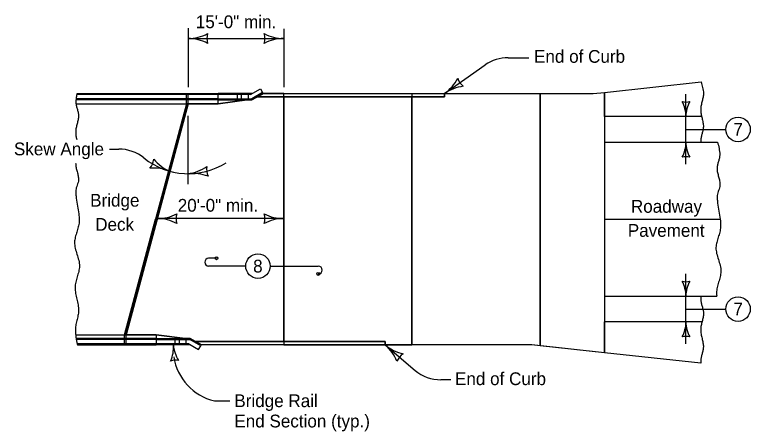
# Model space of a CAD drawing. Extents: x 9234 to 81668, y 5635 to 15999.
# Drawn here: x 18608 to 19530, y 8752 to 9275 of the extents above; entities that cross this region are included whole.
import ezdxf

# ---------------------------------------------------------------- set-up
doc = ezdxf.new("R2010")
doc.units = 0
for name, color, linetype in [('Annotation', 7, 'Continuous'), ('PS_BOLT', 7, 'Continuous'), ('PS_CONST', 7, 'Continuous'), ('PS_DIM', 7, 'Continuous'), ('Revetment', 7, 'Continuous')]:
    doc.layers.add(name, color=color, linetype=linetype)

msp = doc.modelspace()

# ---------------------------------------------------------------- linework, layer by layer
at = {"layer": 'Annotation'}
for p, q in [((18903.37, 9174.38), (18915.74, 9181.52)), ((18915.74, 9181.52), (18918.42, 9176.88)), ((18862.78, 9174.38), (18685.5, 9174.38)), ((18685.89, 9175.72), (18862.78, 9175.72)), ((18823, 9162.99), (18823, 9175.72)), ((18824.99, 9162.99), (18824.99, 9175.72)), ((18862.78, 9162.99), (18862.78, 9175.72)), ((18905.7, 9175.72), (18862.78, 9175.72)), ((18886.41, 9174.38), (18886.41, 9167.68)), ((18891.77, 9174.38), (18891.77, 9167.68)), ((18900.32, 9174.38), (18900.32, 9167.68)), ((18918.42, 9176.88), (18904.81, 9169.02)), ((18919.1, 9175.72), (18905.17, 9167.68)), ((18919.1, 9175.72), (18918.42, 9176.88)), ((18684.38, 9162.99), (18862.78, 9162.99)), ((18862.78, 9167.68), (18684.42, 9167.68)), ((18862.78, 9169.02), (18684.55, 9169.02)), ((18823, 9162.99), (18745.42, 8873.46)), ((18862.78, 9169.02), (18904.81, 9169.02)), ((18862.78, 9167.68), (18905.17, 9167.68)), ((18862.78, 9162.99), (18898.81, 9167.68)), ((18684.01, 8873.46), (18785.2, 8873.46)), ((18785.34, 8868.77), (18684.54, 8868.77)), ((18785.2, 8867.42), (18684.74, 8867.42)), ((18745.42, 8860.72), (18745.42, 8873.46)), ((18747.41, 8860.72), (18747.41, 8873.46)), ((18785.2, 8873.46), (18785.2, 8860.72)), ((18785.2, 8873.46), (18821.23, 8868.77)), ((18785.2, 8868.77), (18827.59, 8868.77)), ((18785.2, 8867.42), (18827.23, 8867.42)), ((18808.83, 8862.06), (18808.83, 8868.77)), ((18814.19, 8862.06), (18814.19, 8868.77)), ((18822.74, 8862.06), (18822.74, 8868.77)), ((18840.85, 8859.56), (18827.23, 8867.42)), ((18834.45, 8864.81), (18827.59, 8868.77)), ((18785.2, 8862.06), (18685.88, 8862.06)), ((18686.3, 8860.72), (18785.2, 8860.72)), ((18828.12, 8860.72), (18785.2, 8860.72)), ((18825.79, 8862.06), (18838.16, 8854.92)), ((18838.16, 8854.92), (18840.85, 8859.56)), ((18841.52, 8860.73), (18840.85, 8859.56))]:
    msp.add_line(p, q, dxfattribs=at)
for points in [[(18903.37, 9174.38), (18862.78, 9174.38), (18862.78, 9174.38), (18862.78, 9174.38)], [(18825.79, 8862.06), (18785.2, 8862.06), (18785.2, 8862.06), (18785.2, 8862.06)]]:
    msp.add_lwpolyline(points, dxfattribs=at)
at = {"layer": 'PS_CONST'}
for centre in [(18860.67, 8969.26), (18988.35, 8949.59)]:
    msp.add_circle(centre, 1.78, dxfattribs=at)
for centre, radius, start, end in [((18764.28, 8857.49), 42.5, 336.29398, 4.36647), ((18849.04, 8863.96), 42.5, 184.36647, 212.43895), ((18809.37, 8825.19), 16.42, 76.63311, 112.09982)]:
    msp.add_arc(centre, radius, start, end, dxfattribs=at)
at = {"layer": 'PS_DIM'}
for p, q in [((18824.99, 9257.53), (18824.99, 9183.59)), ((18945.06, 9256.8), (18945.06, 9183.59)), ((18824.99, 9244.76), (18945.06, 9244.76)), ((19226.51, 9220.7), (19252.26, 9220.7)), ((19146.63, 9175.72), (19197.79, 9211.62)), ((19347.18, 9177.21), (19468.53, 9190.24)), ((18685.89, 9175.72), (18685.89, 9175.72)), ((19449.48, 9087.36), (19449.48, 9174.78)), ((18824.99, 9062.36), (18824.99, 9147.74)), ((19469.3, 9146.9), (19347.18, 9146.9)), ((19449.48, 9130.77), (19478.95, 9130.77)), ((19478.95, 9130.77), (19499.51, 9130.77)), ((19347.18, 9114.73), (19489.28, 9114.73)), ((18726.48, 9106.13), (18738.27, 9106.13)), ((18945.06, 9018.99), (18786.4, 9018.99)), ((19347.18, 9018.22), (19492.49, 9018.22)), ((18860.67, 8969.26), (18850.84, 8969.26)), ((18897.33, 8959.43), (18850.85, 8959.43)), ((18928.05, 8959.43), (18988.35, 8959.43)), ((19449.48, 8862.17), (19449.48, 8949.6)), ((19347.18, 8921.71), (19488.14, 8921.71)), ((19449.48, 8905.58), (19478.95, 8905.58)), ((19478.95, 8905.58), (19499.51, 8905.58)), ((19469.74, 8889.54), (19347.18, 8889.54)), ((18685.95, 8861.81), (18686.3, 8860.72)), ((19072.22, 8860.7), (19109.93, 8828.78)), ((19468.15, 8837.91), (19347.18, 8850.9)), ((19154.51, 8816.94), (19142.24, 8816.94)), ((18857.99, 8790.62), (18877.5, 8790.62))]:
    msp.add_line(p, q, dxfattribs=at)
for points in [[(18945.06, 8864.79), (18834.45, 8864.81), (18827.6, 8868.77), (18822.74, 8868.77), (18821.23, 8868.77), (18785.21, 8873.46), (18747.41, 8873.46), (18824.99, 9162.99), (18862.79, 9162.99), (18898.81, 9167.68), (18905.17, 9167.68), (18905.18, 9167.68), (18910.51, 9170.76), (18912.13, 9171.7), (18945.06, 9171.7)], [(19146.63, 9175.74), (19146.63, 9171.7), (18912.13, 9171.7), (18919.09, 9175.72)], [(19146.63, 9171.7), (19146.63, 9175.72), (19266.76, 9175.72), (19266.76, 8859.54), (19256.29, 8860.66), (19105.91, 8860.69), (19105.91, 9171.7)], [(19347.18, 9177.21), (19347.18, 8850.9), (19266.76, 8859.54), (19266.76, 9175.72), (19333.26, 9175.72)], [(19072.22, 8864.77), (19072.22, 8860.72), (18841.52, 8860.73), (18834.45, 8864.81)]]:
    msp.add_lwpolyline(points, close=True, dxfattribs=at)
msp.add_lwpolyline([(19072.22, 8860.7), (19072.22, 8864.77), (18945.06, 8864.79), (18945.06, 9171.7), (19105.91, 9171.7), (19105.91, 8860.69), (19072.22, 8860.7)], dxfattribs=at)
for centre in [(19514.87, 9130.77), (18912.69, 8959.43), (18912.69, 8959.43), (19514.87, 8905.58)]:
    msp.add_circle(centre, 15.36, dxfattribs=at)
for centre, radius, start, end in [((18824.99, 9296.98), 52.23, 270, 298.07249), ((18868.78, 9244.75), 20.17, 162.26665, 197.73335), ((18901.26, 9244.75), 20.17, 342.26665, 17.73335), ((18945.06, 9296.98), 52.23, 241.92751, 270), ((18824.99, 9192.52), 52.23, 61.92751, 90), ((18945.06, 9192.52), 52.23, 90, 118.07249), ((19226.51, 9170.7), 50, 90, 125.06176), ((19116.63, 9218.47), 52.23, 305.06176, 333.13425), ((19182.47, 9200.87), 20.17, 197.32841, 232.79511), ((19176.63, 9132.97), 52.23, 96.98927, 125.06176), ((19449.48, 9180.59), 15.52, 252.26665, 287.73335), ((19409.31, 9146.9), 40.18, 360, 28.07249), ((19489.66, 9146.9), 40.18, 151.92751, 180), ((19409.31, 9114.73), 40.18, 331.92751, 360), ((19489.66, 9114.73), 40.18, 180, 208.07249), ((18738.27, 9056.13), 50, 51.03773, 90), ((18825.49, 9163.98), 88.71, 231.03773, 302.32505), ((18761.85, 9095.12), 20.17, 319.76199, 355.22869), ((18822.3, 9126.6), 52.23, 219.42285, 247.49534), ((19449.48, 9081.05), 15.52, 72.26665, 107.73335), ((18782.32, 9030.1), 52.23, 67.49534, 95.56783), ((18818.79, 9127.13), 52.23, 276.80986, 304.88235), ((18868.47, 9080.46), 20.17, 169.07651, 204.54321), ((18831.18, 9023.41), 52.23, 68.73737, 96.80986), ((18786.42, 9071.21), 52.23, 270, 298.07249), ((18830.21, 9018.99), 20.17, 162.26665, 197.73335), ((18901.26, 9018.99), 20.17, 342.26665, 17.73335), ((18945.06, 9071.21), 52.23, 241.92751, 270), ((18786.42, 8966.76), 52.23, 61.92751, 90), ((18945.06, 8966.76), 52.23, 90, 118.07249), ((18850.84, 8964.34), 4.92, 90, 270), ((18988.35, 8954.51), 4.92, 270, 90), ((19449.48, 8955.4), 15.52, 252.26665, 287.73335), ((19409.31, 8921.71), 40.18, 360, 28.07249), ((19489.66, 8921.71), 40.18, 151.92751, 180), ((19409.31, 8889.54), 40.18, 331.92751, 360), ((19489.66, 8889.54), 40.18, 180, 208.07249), ((19449.48, 8855.86), 15.52, 72.26665, 107.73335), ((19038.47, 8820.84), 52.23, 21.68043, 49.75292), ((19105.96, 8900.57), 52.23, 229.75292, 257.82541), ((19038.47, 8820.84), 52.23, 49.75179, 49.75293), ((19105.64, 8832.41), 20.17, 122.01957, 157.48627), ((18873.12, 8855.55), 66.66, 188.48278, 256.88228), ((19142.24, 8866.94), 50, 229.75292, 270)]:
    msp.add_arc(centre, radius, start, end, dxfattribs=at)
for points in [[(18685.89, 9175.72), (18684.77, 9170.71), (18684.47, 9168.19), (18684.29, 9165.67), (18684.67, 9161.23), (18685.82, 9156.79), (18687.04, 9152.35), (18687.6, 9147.9), (18687.06, 9142.81), (18685.85, 9137.72), (18684.63, 9132.62), (18684.22, 9130.07), (18684.05, 9127.52), (18684.44, 9122.81), (18685.38, 9118.09)], [(18684.04, 9088.39), (18684.6, 9083.14), (18685.9, 9077.87), (18687.16, 9072.6), (18687.6, 9067.34), (18687.04, 9064.12), (18685.96, 9060.94), (18684.87, 9057.76), (18684.29, 9054.55), (18684.29, 9049.64), (18684.72, 9044.7), (18686.31, 9034.74), (18687.91, 9024.8), (18688.44, 9017.41), (18688.4, 9014.97), (18687.37, 9008.55), (18685.46, 9002.14), (18683.58, 8995.73), (18682.61, 8989.3), (18682.79, 8985.55), (18683.46, 8981.79), (18685.63, 8974.29), (18687.83, 8966.79), (18688.76, 8959.28), (18688.48, 8955.94), (18687.84, 8952.6), (18685.99, 8945.91), (18684.17, 8939.22), (18683.33, 8932.53), (18684.03, 8925.32), (18685.56, 8918.08), (18687.07, 8910.84), (18687.67, 8903.6), (18686.94, 8897.36), (18685.49, 8891.12), (18684.15, 8884.89), (18683.69, 8878.65), (18683.94, 8874.43), (18684.35, 8870.2), (18685.95, 8861.81)]]:
    msp.add_spline(points, degree=3, dxfattribs=at)
at = {"layer": 'Revetment'}
for p, q in [((18919.09, 9175.72), (18905.18, 9167.68)), ((18912.13, 9171.7), (19146.63, 9171.7)), ((18945.06, 9175.72), (18919.09, 9175.72)), ((18945.06, 9018.22), (18945.06, 9175.72)), ((18945.06, 9175.72), (19105.91, 9175.72)), ((19105.91, 9175.72), (19105.91, 9018.22)), ((19105.91, 9175.72), (19333.26, 9175.72)), ((19146.63, 9175.72), (19146.63, 9171.7)), ((19266.76, 9175.72), (19266.76, 8859.54)), ((19333.26, 9175.72), (19347.18, 9177.21)), ((19347.18, 9146.9), (19347.18, 9177.21)), ((19347.18, 9177.21), (19347.18, 9018.22)), ((18824.99, 9162.99), (18747.41, 8873.46)), ((18823, 9162.99), (18784.21, 9018.22)), ((18862.79, 9162.99), (18823, 9162.99)), ((18898.81, 9167.68), (18862.79, 9162.99)), ((18905.18, 9167.68), (18898.81, 9167.68)), ((19347.18, 9146.9), (19347.18, 9114.73)), ((18745.42, 8873.46), (18784.21, 9018.22)), ((18945.06, 9018.22), (18945.06, 8860.73)), ((19105.91, 8860.69), (19105.91, 9018.22)), ((19347.18, 9018.22), (19347.18, 8850.9)), ((19347.18, 8850.9), (19347.18, 8889.54)), ((18785.21, 8873.46), (18745.42, 8873.46)), ((18821.23, 8868.77), (18785.21, 8873.46)), ((18827.6, 8868.77), (18821.23, 8868.77)), ((18841.51, 8860.73), (18827.6, 8868.77)), ((18834.45, 8864.81), (19072.22, 8864.74)), ((18945.06, 8860.73), (18841.51, 8860.73)), ((18945.06, 8860.73), (19105.91, 8860.69)), ((19072.22, 8860.7), (19072.22, 8864.74)), ((19256.29, 8860.66), (19105.91, 8860.69)), ((19347.18, 8850.9), (19256.29, 8860.66))]:
    msp.add_line(p, q, dxfattribs=at)
for points in [[(19468.53, 9190.24), (19469.34, 9186.74), (19470.36, 9183.23), (19471.23, 9179.72), (19471.6, 9176.21), (19471.05, 9171.12), (19469.84, 9166.03), (19468.62, 9160.93), (19468.04, 9155.84), (19468.55, 9150.39), (19469.72, 9144.94), (19470.87, 9139.48), (19471.36, 9134.04), (19470.84, 9129.76), (19469.74, 9125.5), (19468.63, 9121.24), (19468.04, 9116.98), (19468.09, 9114.73)], [(19489.28, 9114.73), (19491, 9106.96), (19491.69, 9103.07), (19491.94, 9099.2), (19491.42, 9094.92), (19490.32, 9090.66), (19489.21, 9086.4), (19488.62, 9082.14), (19489.13, 9076.82), (19490.44, 9071.48), (19491.72, 9066.14), (19492.18, 9060.81), (19491.61, 9057.59), (19490.53, 9054.41), (19489.45, 9051.23), (19488.86, 9048.02), (19488.86, 9043.11), (19489.3, 9038.17), (19490.88, 9028.22), (19492.48, 9018.27), (19493.01, 9010.88), (19492.97, 9008.44), (19491.94, 9002.02), (19490.04, 8995.61), (19488.15, 8989.2), (19487.18, 8982.77), (19487.36, 8979.02), (19488.03, 8975.27), (19490.21, 8967.76), (19492.4, 8960.26), (19493.33, 8952.76), (19493.05, 8949.41), (19492.42, 8946.07), (19490.56, 8939.39), (19488.74, 8932.7), (19487.91, 8926), (19488.14, 8921.71)], [(19468.6, 8921.71), (19468.28, 8917.93), (19468.66, 8913.48), (19469.82, 8909.04), (19471.03, 8904.6), (19471.6, 8900.16), (19471.05, 8895.07), (19469.84, 8889.97), (19468.62, 8884.88), (19468.04, 8879.78), (19468.55, 8874.34), (19469.72, 8868.88), (19470.87, 8863.42), (19471.36, 8857.98), (19470.84, 8853.71), (19469.74, 8849.45), (19468.63, 8845.19), (19468.04, 8840.92), (19468.15, 8837.91)]]:
    msp.add_spline(points, degree=3, dxfattribs=at)

# ---------------------------------------------------------------- texts
at = {"layer": 'PS_BOLT'}
for s, p in [('15\'-0" min.', (18834.75, 9257.68)), ('End of Curb', (19259.01, 9214.28)), ('7', (19508.99, 9122.77)), ('Skew Angle', (18606.61, 9098.3)), ('Bridge', (18702.22, 9033.98)), ('20\'-0" min.', (18812.08, 9027.66)), ('Roadway', (19380.49, 9026.35)), ('Deck', (18708.56, 9003.8)), ('Pavement', (19376.6, 8996.17)), ('8', (18906.66, 8951.42)), ('7', (19508.99, 8897.58)), ('End of Curb', (19159.84, 8810.31))]:
    msp.add_text(s, height=16, dxfattribs=at).set_placement(p)
at = {"layer": 'PS_DIM'}
for s, p in [('Bridge Rail', (18883.1, 8782.71)), ('End Section (typ.)', (18883.1, 8757.26))]:
    msp.add_text(s, height=16, dxfattribs=at).set_placement(p)

doc.saveas('drawing.dxf')
